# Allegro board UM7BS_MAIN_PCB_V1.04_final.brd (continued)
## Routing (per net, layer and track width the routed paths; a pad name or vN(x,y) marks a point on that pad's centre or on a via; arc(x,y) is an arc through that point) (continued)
MDI2-: length 17.8
  LAY3 w0.102: v1(116.23,38.89) 116.36,39.02 116.36,39.11 116.21,39.26 112.69,39.26 111.58,38.15 111.58,36.05 111.18,35.65 v1(110.17,35.65)
  BOTTOM w0.101: v1(116.23,38.89) 116.56,39.22 116.64,39.29 117.64,39.29 117.73,39.2 U22.8
  BOTTOM w0.102: U24.8 106.67,32.7 107.15,33.19 109.08,33.19 109.49,33.6 109.49,35.56 109.71,35.78 110.04,35.78 v1(110.17,35.65)
MDI3+: length 13.2
  LAY3 w0.102: v1(116.87,40.09) 116.76,40.2 116.76,40.64 116.34,41.06 109.91,41.06 109.82,41.14 108.66,41.14 v1(108.52,41.28)
  BOTTOM w0.101: U22.10 117.63,40 117.49,40.14 116.92,40.14 v1(116.87,40.09)
  BOTTOM w0.102: U24.1 106.71,41.59 107.3,41 108.24,41 v1(108.52,41.28)
MDI3-: length 13.1
  LAY3 w0.102: v1(108.52,40.64) 108.66,40.78 109.67,40.78 109.76,40.69 116.19,40.69 116.39,40.49 116.39,40.25 v1(116.23,40.09)
  BOTTOM w0.101: v1(116.23,40.09) 116.64,40.49 117.64,40.49 117.73,40.4 U22.11
  BOTTOM w0.102: U24.2 106.68,40.32 107.06,40.7 108.46,40.7 v1(108.52,40.64)
MIC1L-VREFO: length 10.9
  LAY4 w0.305: v1(24.28,27.44) 23.02,28.7 23.02,31.35 21.67,32.7 21.67,34.39 21.01,35.04 v1(20.79,35.04)
  BOTTOM w0.178: v1(20.79,35.04) U25.31
  BOTTOM w0.305: v1(24.28,27.44) 24.28,27.43 R337.2
MIC1R-VREFO: length 9
  LAY4 w0.305: v1(20.73,27.46) 21.11,27.85 21.11,34.13 v1(20.79,34.45)
  BOTTOM w0.178: v1(20.79,34.45) 20.92,34.45 21.12,34.64 U25.30
  BOTTOM w0.305: R335.2 v1(20.73,27.46)
MIC2-VREFO: length 13.9
  LAY4 w0.305: v1(24.31,26.71) 20.75,26.71 20.08,27.39 20.08,33.56 v1(20.48,33.97)
  BOTTOM w0.178: v1(20.48,33.97) 20.99,33.97 21.26,34.24 U25.29
  BOTTOM w0.305: v1(24.31,26.71) 24.93,27.33 R333.1
MIC_SEL_DET: length 99.7
  LAY3 w0.102: v1(42.25,74.8) 42.25,73.91 33.84,65.5 33.84,47.05 30.76,43.97 24.64,43.97 24.28,44.33 21.63,44.33 21.25,43.95 21.25,37.84 19.56,36.16 19.56,27.58 20.88,26.26 25.67,26.26 v1(26.75,25.17)
  BOTTOM w0.102: R404.2 44.51,75.08 44.23,74.8 v1(42.25,74.8)
  BOTTOM w0.254: R340.1 26.76,25.18 v1(26.75,25.17) 26.05,25.17 R349.1 25.79,25.32 Q36.1 26.73,23.09 28.47,23.09 30.05,21.51 37.15,21.51 38.29,20.37 38.29,15.85 36.4,13.96 J2.6
MIC_SEL_SPDIF: length 86
  LAY3 w0.102: v1(50.95,76.13) 51.66,75.42 51.66,61.33 51.13,60.81 51.13,59.97 51.39,59.71 51.39,55.83 50.72,55.16 50.72,46.45 v1(49.41,45.14)
  LAY4 w0.102: v1(27.32,22.03) 28.65,22.03 34.88,28.26 34.88,37.48 v1(31.71,40.64) ; v1(49.41,45.14) 48.58,44.31 31.65,44.31 v1(31.48,44.13)
  BOTTOM w0.102: v1(31.48,44.13) 31.19,43.85 31.19,42.86 30.68,42.35 30.68,41.1 R346.2 ; R346.2 31.14,40.38 28.36,37.61 27.79,37.61 27.66,37.74 U25.48 ; R346.2 v1(31.71,40.64) ; R450.2 50.94,76.12 v1(50.95,76.13) ; Q36.3 v1(27.32,22.03)
OVPA: length 36.6
  TOP w0.305: v1(121.9,84.01) 121.8,84.01 121.38,84.42 121.38,87.1 121,87.48 117.84,87.48 117.26,88.06 109.3,88.06 108.51,88.84 108.51,93.84 107.18,95.17 107.18,97.46 108.43,98.71 114.06,98.71
  BOTTOM w0.305: v1(121.9,84.01) 123.73,84.01 123.98,84.25 U41.7
PCIE_LAN_WAKE#: length 42.8
  LAY3 w0.102: v1(132.77,43.5) 143.7,43.5 146.63,46.43 154.99,46.43 157.31,48.75 v1(157.31,49.56)
  BOTTOM w0.102: R95.2 156.76,56.58 158.3,55.04 158.3,51.13 157.31,50.14 v1(157.31,49.56) ; v1(132.77,43.5) 129.73,40.47 R304.2
PCIE_RXN0_LAN: length 61.8
  TOP w0.089: v1(175.4,59.63) 175.63,59.41 U1.J20
  LAY3 w0.112: v1(175.4,59.63) 175.03,59.26 175.03,58.99 174.71,58.66 172.84,58.66 171.71,57.53 167.75,57.53 166.81,58.46 163.04,58.46 160.7,56.12 160.7,54.78 157.48,51.56 157.48,51.03 157.12,50.67 156.77,50.67 154.66,48.56 152.05,48.56 151.67,48.95 146.25,48.95 142.08,44.78 130.11,44.78 128.6,46.29 126.38,46.29 v1(126.12,46.03)
  BOTTOM w0.124: v1(126.12,46.03) 125.84,46.3 125.1,46.3 124.93,46.13 124.93,45.24 C346.1
PCIE_RXN1_WLAN: length 169.3
  TOP w0.089: v1(173.88,59.63) 174.2,59.3 U1.F20
  TOP w0.124: CN26.43 238.92,18.27 239.05,18.4 239.52,18.4 240.34,19.22 240.34,20.43 240.47,20.55 240.62,20.55 v1(240.89,20.28)
  LAY3 w0.089: v1(173.88,59.63) 173.67,59.84 173.67,59.9 173.79,60.02 177.75,60.02 178.08,60.35 178.08,60.76 178.76,61.44 178.76,62.57 179.1,62.91 179.11,62.91 179.12,62.92 179.14,62.92 179.14,62.91 179.21,62.98 179.21,63.05 179.21,63.05 179.21,63.07
  LAY3 w0.099: 179.21,63.07 179.21,67.71 179.44,67.94 179.44,74.54 179.45,74.54 179.45,74.57
  LAY3 w0.112: v1(240.89,20.28) 240.52,20.65 239.52,20.65 238.01,22.16 238.01,35.78 226.37,47.42 226.37,90.82 218.05,99.13 216.97,99.13 215.88,98.05 208.01,98.05 201.23,91.27 188.71,91.27 187.53,90.08 187.53,84.23 185.22,81.93 181.52,81.93 179.15,79.56 179.15,75.45 179.45,75.15 179.45,74.57
PCIE_RXP0_LAN: length 61.8
  TOP w0.089: v1(174.52,59.63) 174.92,59.23 U1.G20
  LAY3 w0.112: v1(126.12,46.8) 126.38,46.53 128.7,46.53 130.21,45.02 141.98,45.02 146.15,49.18 151.77,49.18 152.15,48.8 154.56,48.8 156.67,50.91 157.02,50.91 157.24,51.12 157.24,51.66 160.46,54.88 160.46,56.22 162.94,58.7 166.91,58.7 167.85,57.76 171.61,57.76 172.75,58.9 174.61,58.9 174.79,59.09 174.79,59.35 v1(174.52,59.63)
  BOTTOM w0.124: C347.1 124.68,45.24 124.68,46.24 124.99,46.55 125.87,46.55 v1(126.12,46.8)
PCIE_RXP1_WLAN: length 169.4
  TOP w0.089: U1.D20 173.53,59.34 v1(173.25,59.63)
  TOP w0.124: CN26.41 238.9,18.77 239.02,18.65 239.42,18.65 240.09,19.33 240.09,20.53 240.36,20.8 240.8,20.8 v1(240.89,20.89)
  LAY3 w0.089: v1(173.25,59.63) 173.45,59.84 173.45,59.99 173.7,60.24 177.66,60.24 177.86,60.44 177.86,60.81 178.57,61.51 178.57,62.65 178.97,63.05 178.97,63.05 178.99,63.07
  LAY3 w0.099: 179.21,74.57 179.21,74.54 179.21,74.54 179.21,68.03 178.99,67.81 178.99,63.07
  LAY3 w0.112: v1(240.89,20.89) 239.62,20.89 238.25,22.26 238.25,35.88 226.6,47.52 226.6,90.92 218.15,99.37 216.87,99.37 215.78,98.29 207.91,98.29 201.13,91.5 188.61,91.5 187.29,90.18 187.29,84.33 185.12,82.17 181.42,82.17 178.91,79.66 178.91,75.35 179.21,75.05 179.21,74.57
PCIE_TXN0_LAN: length 61.7
  TOP w0.124: C4.2 167.97,61.28 167.54,61.28 167.53,61.27 164.83,61.27 v1(164.48,60.92)
  LAY3 w0.112: v1(128.3,48.45) 128.44,48.59 128.44,48.71 128.55,48.82 131.88,48.82 133.76,50.71 152.88,50.71 156.05,53.87 157.19,53.87 158.66,55.34 158.66,56.95 163,61.29 163.92,61.29 164.29,60.92 v1(164.48,60.92)
  BOTTOM w0.124: v1(128.3,48.45) 128.3,48.35 128.18,48.22 127.95,48.22 127.82,48.35 127.82,48.59 127.69,48.71 121.38,48.71 120.52,47.86 120.52,43.28 120.66,43.13 120.66,42 120.73,41.94 U22.18
PCIE_TXN1_WLAN: length 186.4
  TOP w0.124: CN26.37 238.8,19.77 238.93,19.9 239.31,19.9 239.59,20.18 239.59,21.8 240.45,22.66 240.45,23.79 240.16,24.08 239.7,24.08 v1(239.53,24.25) ; v1(167.39,98.62) 167.16,98.39 167.16,97.27 166.72,96.83 166.72,92.06 164.37,89.7 162.85,89.7 160.52,87.37 160.52,70.48 162.03,68.97 163.61,68.97 163.85,69.21 C6.2
  LAY3 w0.112: v1(239.53,24.25) 239.66,24.12 240.8,24.12 241.99,25.32 241.99,34.67 228.39,48.27 228.39,92.06 218.74,101.71 218.03,101.71 217.68,101.35 214.48,101.35 214.05,101.78 211.17,101.78 209.13,99.74 190.97,99.74 190.04,100.67 168.76,100.67 167.15,99.06 167.15,98.87 v1(167.39,98.62)
PCIE_TXP0_LAN: length 61.3
  TOP w0.124: v1(164.48,61.53) 164.72,61.53 164.72,61.52 167.86,61.52 C3.2
  LAY3 w0.112: v1(164.48,61.53) 162.9,61.53 158.42,57.05 158.42,55.43 157.1,54.11 155.95,54.11 152.78,50.94 133.67,50.94 131.78,49.06 128.44,49.06 v1(128.3,49.2)
  BOTTOM w0.124: v1(128.3,49.2) 128.07,48.97 121.27,48.97 120.27,47.96 120.27,43.17 120.41,43.03 120.41,42.05 120.33,41.97 U22.17
PCIE_TXP1_WLAN: length 187.3
  TOP w0.124: CN26.35 238.84,20.27 238.96,20.15 239.2,20.15 239.34,20.28 239.34,21.9 240.2,22.76 240.2,23.69 240.05,23.83 239.72,23.83 v1(239.53,23.64) ; C5.2 163.85,68.44 163.57,68.71 161.92,68.71 160.27,70.37 160.27,87.47 162.75,89.96 164.26,89.96 166.47,92.16 166.47,96.93 166.91,97.38 166.91,98.37 v1(166.66,98.62)
  LAY3 w0.112: v1(239.53,23.64) 239.78,23.89 240.9,23.89 242.23,25.22 242.23,34.77 228.63,48.37 228.63,92.16 218.84,101.95 217.94,101.95 217.58,101.59 214.58,101.59 214.15,102.02 211.07,102.02 209.03,99.98 191.07,99.98 190.14,100.91 168.66,100.91 166.91,99.16 166.91,98.87 v1(166.66,98.62)
PCIE_WIFI_WAKE#: length 178.3
  LAY3 w0.102: v1(189.18,90.72) 201.79,90.72 208.62,97.55 217.02,97.55 218.21,96.37 219.46,96.37 225.42,90.41 225.42,46.31 235.12,36.61 v1(235.12,14.78)
  LAY4 w0.102: v1(159.74,60.19) 160.32,60.19 167.75,67.63 167.75,71.95 169.81,74.01 169.81,79.19 172.32,81.7 177.46,81.7 179.63,79.54 181.38,79.54 182.99,81.15 184.13,81.15 189.28,86.3 189.28,90.63 v1(189.18,90.72)
  BOTTOM w0.102: v1(159.74,60.19) 157.66,60.19 156.76,59.29 R97.2 ; R787.1 v1(235.12,14.78)
PD#: length 10.8
  LAY4 w0.102: v1(32.13,36.29) 30.37,38.04 v1(28.24,38.04)
  BOTTOM w0.102: U26.4 33.32,35.1 v1(32.13,36.29)
  BOTTOM w0.114: U25.47 26.63,37.96 26.97,38.31 27.98,38.31 v1(28.24,38.04)
PERSTB: length 3.1
  BOTTOM w0.114: R306.1 125.37,42.13 125.37,41.65 124.53,40.8 U22.25
PM_BATLOW#: length 112.9
  TOP w0.089: 168.41,57.59 168.46,57.59 168.89,57.15 R122.1
  TOP w0.102: R122.1 169.98,57.15 170.75,56.38 171.37,56.38 171.48,56.49 172.02,56.49 172.12,56.6 172.36,56.6 172.67,56.29 U1.C14 ; v1(149.65,58.88) 149.9,58.63 163.77,58.63 164.81,57.59 168.41,57.59
  LAY3 w0.102: v1(85.97,56.4) 85.99,56.38 95.61,56.38 97.43,58.19 103,58.19 105.23,60.42 110.48,60.42 113.66,57.24 115.63,57.24 116.61,58.22 122.12,58.22 123.02,57.32 125.08,57.32 125.33,57.07 146.28,57.07 148.19,58.98 149.55,58.98 v1(149.65,58.88)
  LAY4 w0.102: v1(85.97,56.4) 84.61,57.75 79.61,57.75 78.53,58.83 72.64,58.83 71.36,60.11 v1(69.03,60.11)
  BOTTOM w0.102: v1(69.03,60.11) R448.1 R447.1
PM_RSMRST#: length 133.3
  TOP w0.102: U1.F18 173.88,57.92 v1(173.88,57.72)
  LAY3 w0.102: v1(152.19,68.88) 142.63,68.88 137.4,74.12 124.88,74.12 124.08,74.91 121.05,74.91 120.74,74.6 118.56,74.6 118.25,74.91 103.43,74.91 100.88,72.36 84.44,72.36 84.11,72.03 77.57,72.03 77.23,72.36 74.34,72.36 71.77,69.8 71.77,64.08 v1(71.87,63.98)
  LAY4 w0.127: v1(152.19,68.88) 152.19,68.19 158.49,61.88 158.49,60.13 159.55,59.07 167.03,59.07 167.46,59.5 v1(167.46,60.59)
  BOTTOM w0.102: v1(71.87,63.98) 71.87,63.49 70.85,62.47 68.08,62.47 67.39,61.78 R591.2 ; v1(173.88,57.72) 173.44,58.17 172.55,58.17 172.38,58 172.14,58
  BOTTOM w0.114: R393.1 65.14,63.93 65.72,63.93 66,64.21 66.49,64.21 66.83,63.87 66.83,62.34 R591.2 ; R82.1 170.22,60.46 170.86,59.81 170.86,58.56 171.42,58 172.14,58
  BOTTOM w0.127: v1(167.46,60.59) 167.46,60.75 167.69,60.98 169.5,60.98 R82.1
PM_SLP_S0IX#: length 105.3
  LAY3 w0.102: v1(58.95,75.74) 58.95,75.69 58.27,75.01 58.27,69.47 56.69,67.88 56.69,62 57.74,60.95 57.74,59.36 56.69,58.31 56.69,54.84 v1(56.96,54.57) ; v1(106.76,80.87) 104.73,80.87 103.72,79.85 102.2,79.85 99.86,77.51 88.82,77.51 86.94,79.39 77.51,79.39 71.05,72.94 71.05,58.16 71.86,57.35 v1(71.86,56.39)
  LAY4 w0.102: v1(56.96,54.57) 57.21,54.81 60.95,54.81 61.62,55.49 69.76,55.49 70.66,56.39 v1(71.86,56.39)
  BOTTOM w0.102: C566.2 75.27,55.78 72.46,55.78 v1(71.86,56.39) ; R225.2 108.65,80.87 v1(106.76,80.87)
  BOTTOM w0.114: R442.1 v1(58.95,75.74) ; C566.2 75.91,57.17 76.17,57.43 U6.7
PM_SLP_S3#: length 157.2
  LAY3 w0.203: v1(72.89,58.12) 73.33,57.68 77.3,57.68 79.14,55.84 80.15,55.84 81.22,56.9 81.22,59.04 81.76,59.58 83.28,59.58 83.49,59.37 91.2,59.37 94.08,62.26 115.17,62.26 117.14,60.28 120.18,60.28 120.83,59.64 129.93,59.64 130.89,60.6 138.25,60.6 v1(138.57,60.28)
  LAY4 w0.203: v1(160.09,67.44) 164.81,67.44 165.68,68.31 v1(167.07,68.31) ; v1(142.98,45.04) 143.56,45.62 143.56,50.42 138.89,55.09 138.89,59.96 v1(138.57,60.28) ; v1(72.89,58.12) 72.31,58.7 68.05,58.7 67.76,58.41 52.96,58.41 52.36,59.02 v1(50.46,59.02)
  BOTTOM w0.114: C23.2 75.93,58.23 75.94,58.23 U6.9
  BOTTOM w0.152: v1(72.89,58.12) 73.23,57.78 75.04,57.78 75.27,58.01 C23.2
  BOTTOM w0.203: v1(138.57,60.28) 143.15,60.28 144.25,61.38 148.55,61.38 149.04,60.9 154.69,60.9 159.09,65.3 R219.1 159.22,66.51 160.09,67.38 v1(160.09,67.44) ; U31.70 49.61,59.86 v1(50.46,59.02) ; R557.1 142.97,45.04 v1(142.98,45.04) ; R3112.2 168.11,68.68 167.75,68.31 v1(167.07,68.31)
PM_SLP_S4#: length 32.8
  LAY4 w0.152: v1(72.55,56.38) 72.04,56.89 52.78,56.89 51.55,58.12 49.93,58.12 v1(48.7,59.34)
  BOTTOM w0.152: v1(72.55,56.38) 72.8,56.13 74.92,56.13 75.27,56.47 C24.2 75.55,57.21 76.17,57.83 U6.8 ; v1(48.7,59.34) 48.59,59.46 U31.69
PMC_ACPRESENT: length 9.5
  TOP w0.102: U1.C13 172.46,55.95 172.15,55.95 172.01,56.08 171.68,56.08
  TOP w0.114: v1(166.41,56.87) 166.88,56.4 170.02,56.4 170.47,55.95 171.55,55.95 171.68,56.08
  BOTTOM w0.102: v1(166.41,56.87) 166.35,56.8 R127.2 165.77,56.26 165.27,56.77 Q8.3
PMC_PLTRST: length 133.4
  LAY3 w0.102: v1(183.32,37.76) 180.55,37.76 180.36,37.56 176.96,37.56 175.17,39.35 175.17,41.18 173.79,42.56 173.79,45.89 ; v1(142.8,63.93) 134.46,72.27 128.56,72.27 128.36,72.07 119.36,72.07 118.64,71.35 118.64,67.43 114.49,63.29 93.11,63.29 91.3,61.49 83.38,61.49 v1(82.94,61.04)
  LAY3 w0.127: v1(166.96,52.03) 166.96,51.65 167.81,50.8 168.36,50.8 168.93,50.24 170.74,50.24 171.57,49.41 171.99,49.41 173.79,47.61 173.79,45.89
  LAY4 w0.127: v1(166.96,52.03) 165.91,52.03 162.52,55.41 159.86,55.41 153.33,61.94 149.19,61.94 148.77,62.37 144.36,62.37 v1(142.8,63.93)
  BOTTOM w0.102: v1(82.94,61.04) 82.47,61.04 TP15.1 80.72,59.3 79.29,59.3 78.63,58.63 U6.2
  BOTTOM w0.114: R166.1 183.34,37.74 v1(183.32,37.76) ; v1(166.96,52.03) 166.55,51.62 R602.2
PMC_PWRBTN#: length 118.7
  TOP w0.102: U1.M16 176.67,56.9 v1(176.67,56.83)
  TOP w0.114: R415.1 78.55,67.88 79.67,66.76 v1(79.67,66.74)
  LAY3 w0.102: v1(79.67,66.74) 84.85,66.74 86.84,64.75 114.88,64.75 117.88,67.75 117.88,71.67 119.1,72.89 127.66,72.89 127.86,73.09 136.86,73.09 147,62.95 v1(147,62.79)
  LAY4 w0.102: v1(166.86,55.52) 166.09,55.52 164.7,56.9 158.89,56.9 153.42,62.37 149.34,62.37 148.93,62.79 v1(147,62.79)
  BOTTOM w0.102: v1(166.86,55.52) 166.86,54.68 167.93,53.61 169.86,53.61 170.26,54.02 R121.2 171.4,54.32 171.72,54.64 171.72,55.33 172.59,56.2 176.04,56.2 v1(176.67,56.83)
  BOTTOM w0.114: v1(79.67,66.74) 79.18,67.23 U30.4
PMC_PWRBTN#_EC: length 33.9
  TOP w0.114: v1(75.05,67.5) 75.43,67.88 R415.2
  LAY4 w0.102: v1(55.6,67.9) 55.75,67.76 74.79,67.76 v1(75.05,67.5)
  BOTTOM w0.114: U30.8 75.95,67.23 75.68,67.5 v1(75.05,67.5) 75.27,67.28 R416.1 ; v1(55.6,67.9) 55.6,65.59 58.04,63.15 60.5,63.15 60.81,63.46 U31.18
PMC_RSTBTN: length 153.6
  TOP w0.102: 184.55,48.85 184.55,49.34 184.29,49.6 184.29,50.04 U1.AF2
  TOP w0.114: v1(185.69,44.08) 185.27,44.51 185.27,46.28 R119.1 185.87,47.52 184.55,48.85 ; v1(79.08,67.96) 78.26,68.77 R412.1 R118.1 R124.2
  LAY3 w0.102: v1(185.69,44.08) 185.54,43.93 185.54,38.28 184.59,37.34 184.59,36.19 183.77,35.37 175.9,35.37 171.92,39.34 171.92,40.86 165.19,47.6 v1(164.72,47.6) ; v1(147.5,60.49) 147.48,60.5 147.48,62.92 136.96,73.45 127.87,73.45 127.67,73.25 119.09,73.25 117.67,71.83 117.67,67.83 114.79,64.95 87.99,64.95 84.99,67.96 v1(79.08,67.96)
  LAY4 w0.102: v1(164.72,47.6) 163.45,48.86 159.05,48.86 157.45,50.46 156.75,50.46 152.96,54.25 152.96,59.22 151.7,60.49 v1(147.5,60.49)
  BOTTOM w0.114: U30.3 78.75,67.63 v1(79.08,67.96)
PMC_SLP_S0IX: length 150
  TOP w0.102: v1(85.62,60.93) 85.62,61.09 94.42,69.89 103.23,69.89 106.2,66.92 106.2,52.76 106.78,52.18 109.31,52.18 111.02,53.89 120.21,53.89 122.67,56.35 137.04,56.35 137.98,57.28 148.19,57.28 v1(148.6,57.68)
  TOP w0.114: v1(157.26,27.91) 157.75,27.91 159.24,26.43 U11.61 ; R206.1 153.67,17.51 v1(153.23,17.51)
  LAY3 w0.102: v1(157.26,27.91) 157.91,27.26 157.91,19.13 157.01,18.23 153.95,18.23 v1(153.23,17.51)
  LAY4 w0.102: v1(157.26,27.91) 157.38,28.02 157.38,33.85 153.78,37.44 153.78,46.03 148.6,51.21 v1(148.6,57.68)
  BOTTOM w0.102: v1(85.62,60.93) 85.62,57.55 83.1,55.03 79.11,55.03 78.16,55.97 R605.2 78.16,56.7 U6.5
PMC_SLP_S3: length 126.3
  TOP w0.114: v1(157.27,27.36) 157.92,27.36 158.84,26.44 U11.62 ; v1(153.29,18.12) 153.46,18.12 R203.1
  LAY3 w0.102: v1(82.21,58.78) 91.77,58.78 93.59,60.61 102.9,60.61 103.58,61.3 115.15,61.3 116.86,59.58 117.92,59.58 118.56,58.94 125.71,58.94 126.93,57.72 137.37,57.72 140.2,60.54 145.76,60.54 146.63,59.67 v1(147.95,59.67) ; v1(153.29,18.12) 153.64,18.47 156.68,18.47 157.66,19.45 157.66,26.96 v1(157.27,27.36)
  LAY4 w0.102: v1(147.95,59.67) 147.95,59.19 148.99,58.15 148.99,51.25 154.26,45.97 154.26,37.29 157.67,33.88 157.67,27.76 v1(157.27,27.36)
  BOTTOM w0.102: U6.3 79.08,58.23 R604.2 79.64,58.79 TP12.1
PMC_SLP_S4: length 112.4
  TOP w0.114: U11.63 158.44,26.44 158.08,26.8 v1(157.25,26.8)
  LAY3 w0.102: v1(83.56,57.18) 83.65,57.28 95.27,57.28 96.6,58.62 102.97,58.62 105.03,60.68 110.56,60.68 113.71,57.52 115.41,57.52 116.34,58.46 122.28,58.46 123.15,57.59 126.14,57.59 126.44,57.3 145.85,57.3 v1(147.39,58.84)
  LAY4 w0.102: v1(147.39,58.84) 148.2,58.04 148.2,51.18 152.45,46.93 152.45,38.49 156.56,34.37 156.56,27.49 v1(157.25,26.8)
  BOTTOM w0.102: U6.4 78.83,57.83 R603.2 80.48,56.19 TP13.1 81.45,56.19 81.69,56.43 82.81,56.43 v1(83.56,57.18)
PMC_SUS_STAT#: length 116.9
  TOP w0.102: U1.D14 173.53,56.1 v1(173.25,55.82) ; R440.1 78.01,61.42 78.65,62.06 v1(78.65,62.25)
  LAY3 w0.102: v1(78.65,62.25) 90.86,62.25 92.25,63.64 114.34,63.64 118.28,67.58 118.28,71.5 119.26,72.47 128.03,72.47 128.23,72.67 135.18,72.67 142.8,65.05 v1(142.8,64.53)
  LAY4 w0.102: v1(166.95,53.56) 166.95,54.41 167.92,55.38 167.92,57.25 167.61,57.56 158.77,57.56 153.58,62.75 149.28,62.75 147.98,64.05 143.28,64.05 v1(142.8,64.53)
  BOTTOM w0.102: v1(166.95,53.56) 167.2,53.31 170.15,53.31 170.84,54 171.45,54 172.03,54.58 172.03,54.95 172.9,55.82 v1(173.25,55.82)
  BOTTOM w0.114: U32.5 78.41,62.76 78.65,62.52 v1(78.65,62.25)
PMC_SUSPWRDNACK: length 159.2
  TOP w0.102: 183.12,49.57 183.39,49.83 183.39,49.95 183.54,50.1 183.54,50.4 U1.AE3 ; v1(184.44,44.38) 184.01,44.81 184.01,46.46 R86.1
  TOP w0.114: 183.12,49.57 183.12,48.43 184.44,47.11 R86.1
  LAY3 w0.102: v1(184.44,44.38) 184.82,44.01 184.82,38.51 183.92,37.61 183.92,36.64 183.39,36.12 176.28,36.12 173.9,38.5 173.9,39.94 171.24,42.59 171.24,44.97 166.49,49.71 v1(164.45,49.71) ; v1(72.56,64.37) 73.68,65.48 73.68,70.58 75.01,71.92 76.18,71.92 76.57,71.53 84.34,71.53 84.73,71.92 101,71.92 103.48,74.4 107.65,74.4 108.54,73.51 127.27,73.51 127.52,73.75 137.18,73.75 148.14,62.79 v1(148.14,60.91)
  LAY4 w0.102: v1(164.45,49.71) 158.49,49.71 157.54,50.66 156.84,50.66 153.27,54.23 153.27,59.64 152.13,60.78 148.27,60.78 v1(148.14,60.91)
  BOTTOM w0.114: v1(72.56,64.37) 72.29,64.64 R429.1 71.1,65.11 Q43.1
PMIC_EN: length 156.2
  TOP w0.102: v1(148.63,19.44) 148.99,19.08 151.15,19.08 151.92,18.31 R553.2
  TOP w0.114: R553.2 153.38,19.06 155.5,19.06 156.82,20.39 U11.13
  LAY3 w0.102: v1(88.97,60.28) 91.45,60.28 93.9,62.73 115.39,62.73 v1(116.57,61.55) 117.54,60.58 120.52,60.58 121.1,60 129.42,60 130.57,61.15 137.35,61.15 v1(138.58,62.38)
  LAY4 w0.102: v1(148.63,19.44) 148.63,27.2 146.77,29.05 146.77,37.97 148.94,40.13 148.94,44.91 148.5,45.35 148.5,47.92 139.96,56.46 139.96,61.01 v1(138.58,62.38) ; v1(50.01,52.97) 50.5,53.46 61.38,53.46 62.42,54.51 80.22,54.51 80.85,55.13 86.13,55.13 88.97,57.98 v1(88.97,60.28)
  BOTTOM w0.102: R552.2 v1(50.01,52.97)
  BOTTOM w0.203: v1(116.57,61.55) 116.73,61.38 R187.2
PMU_SUSCLK: length 245.6
  TOP w0.089: U1.C15 172.51,56.87 172.23,56.87 171.88,57.22 170.59,57.22 170.01,57.8 168.41,57.8
  TOP w0.102: v1(166.05,58.01) 166.26,57.8 168.41,57.8
  LAY3 w0.102: v1(166.05,58.01) 165.92,57.88 165.07,57.88 157.25,50.06 156.86,50.06 154.81,48 150.4,48 149.17,46.77 147.34,46.77 v1(147.28,46.83) 146.4,46.83 145.19,45.61 144.68,45.61 143.04,43.97 122.92,43.97 118.47,48.42 98.06,48.42 94.52,44.89 v1(94.32,44.89) ; v1(234.05,16.47) 227.65,10.07 196.53,10.07 v1(195.68,10.92)
  LAY4 w0.102: v1(142.82,12.1) 142.82,17.7 145.45,20.32 145.45,24.02 144.48,24.98 140.28,24.98 139.47,25.79 139.47,27.08 144.44,32.05 144.44,43.98 v1(147.28,46.83)
  BOTTOM w0.102: v1(94.32,44.89) 90.19,40.76 88.98,40.76 84.64,36.42 R561.1 ; v1(195.68,10.92) 195.48,10.92 192.61,8.06 152.13,8.06 149.8,10.39 145.91,10.39 144.2,12.1 v1(142.82,12.1) ; v1(234.05,16.47) 234.01,16.51 R788.2
POWSW#: length 25.8
  TOP w0.305: SW1.1 121.46,10.63 v1(123.74,10.63)
  BOTTOM w0.305: R499.1 139.03,20.98 137.72,20.98 D22.N D23.N 136.93,18.96 136.07,18.09 129.48,18.09 123.74,12.36 v1(123.74,10.63)
PROCHOT#_EC: length 6.6
  TOP w0.102: U33.2 50.39,62.05 51.02,61.42 R464.2 R456.2 49.58,61.33 v1(49.46,61.45)
  BOTTOM w0.102: U31.76 48.64,62.26 v1(49.46,61.45)
PS_LATCH#: length 8.3
  BOTTOM w0.305: R500.1 133.64,21.43 134.1,20.98 D22.P 135.97,20.98 136.42,21.42 Q45.1 136.42,23.84 137.57,24.99 R498.1
PSELF: length 3.1
  TOP w0.102: U9.17 169.8,93.33 R178.1 R177.2
PSMS: length 2
  BOTTOM w0.102: U95.20 73.27,96.98 72.32,97.93 R800.1
PWM: length 3.7
  BOTTOM w0.305: U41.16 118.89,89.42 R531.1 R530.2 R534.1 R528.1
PWR_LED_WHITE: length 98.3
  TOP w0.102: v1(101.93,10.33) 101.93,14.42 Q16.1
  LAY3 w0.102: v1(51.13,54.18) 51.13,50.78 53.15,48.76 53.15,44.57 51.89,43.3 v1(51.89,36.99)
  LAY4 w0.102: v1(51.89,36.99) 54.78,34.1 54.78,16.95 57.86,13.86 67.14,13.86 70.8,10.2 89.3,10.2 91.87,12.77 96.36,12.77 98.93,10.2 101.8,10.2 v1(101.93,10.33)
  BOTTOM w0.102: v1(51.13,54.18) 51.13,54.19 U31.56
PWR_SW: length 17.6
  TOP w0.305: v1(76.26,99.19) 73.85,99.19 71.3,96.65 CN23.4
  BOTTOM w0.305: U95.24 75.27,97.33 76.26,98.31 C704.1 v1(76.26,99.19)
PWRONLATCHG: length 15.5
  TOP w0.305: Q44.4 138.26,19.22 v1(139.38,18.1)
  BOTTOM w0.305: R498.2 138.53,25.52 C465.1 R496.1 141.57,25.52 141.97,25.12 141.97,18.83 141.24,18.1 v1(139.38,18.1)
R_OUT+: length 1.6
  TOP w0.508: CN12.1 R361.1
R_OUT-: length 1.6
  TOP w0.508: CN12.2 R360.1
REXT: length 2
  BOTTOM w0.102: U16.26 150.71,92.27 149.81,91.37 R267.2
RLV_AMP: length 2.5
  BOTTOM w0.102: U16.27 150.31,92.18 149.91,91.77 149.23,91.77 149.04,91.59 R266.2
RLV_CFG: length 2.4
  BOTTOM w0.102: U16.22 152.31,91.35 R275.2 R274.1
RLV_LNK: length 10.4
  TOP w0.203: v1(152.6,88.3) 152.48,88.18 v1(152.48,84.19)
  BOTTOM w0.152: v1(152.6,88.3) R273.1 152.6,91.83 152.71,91.95 U16.21
  BOTTOM w0.203: U18.7 152.16,83.67 152.48,83.99 v1(152.48,84.19)
RSET: length 5.7
  BOTTOM w0.114: U22.46 119.53,35.29 119.24,35 118.83,35 118.1,34.26 118.1,31.92 118.21,31.82 R297.1
RSMRST#_EC: length 2.6
  BOTTOM w0.114: R393.2 63.65,64.19 62.52,63.06 U31.19
RSMRST_PWRGD: length 179.2
  TOP w0.102: v1(153.8,14.65) 154.06,14.91 R208.1
  LAY3 w0.102: v1(47.78,70.03) 48.07,69.74 48.07,64.71 47.38,64.02 47.38,52.98 47.95,52.42 47.95,39.92 48.48,39.38 v1(48.48,37.27)
  LAY4 w0.102: v1(48.48,37.27) 48.84,37.62 57.9,37.62 58.63,36.9 67.91,36.9 69.21,38.2 87.08,38.2 97.11,48.23 105,48.23 106.88,46.35 106.88,19.29 110.85,15.32 127.55,15.32 130.51,12.35 141.05,12.35 141.72,11.67 143.13,11.67 145.63,14.17 152.23,14.17 152.71,14.65 v1(153.8,14.65)
  BOTTOM w0.114: v1(47.78,70.03) 47.55,70.26 U31.96
RSTZ: length 3.3
  BOTTOM w0.254: U95.22 74.27,98.09 C707.1 R802.2 R801.2
RTA: length 1
  BOTTOM w0.203: R958.2 U41.8
RUNTIME_SCI#_EC: length 21.3
  TOP w0.102: v1(76.75,66.18) 76.64,66.07 v1(69.7,66.07)
  TOP w0.114: R417.2 76.75,66.5 v1(76.75,66.18)
  LAY3 w0.102: v1(69.7,66.07) 69.7,59.15 v1(68.42,57.87)
  BOTTOM w0.102: v1(68.42,57.87) 67.91,58.38 R430.1 64.49,58.38 D10.P
  BOTTOM w0.114: v1(76.75,66.18) 76.76,66.19 U30.7
SA0_DIM0: length 4.8
  TOP w0.102: R147.1 210.15,42.62 R150.1 210.6,41.99 210.6,40.44 210.89,40.15 CN1.197
SA1_DIM0: length 3.6
  TOP w0.102: R590.1 209.37,39.29 R151.1
  TOP w0.114: R151.1 209.95,39.29 210.29,38.95 CN1.201
SATA_DEVSLP0: length 150.3
  TOP w0.102: R24.2 187.13,44.6 186.99,44.46 v1(186.99,43.44)
  LAY3 w0.102: v1(148.75,59.66) 148.34,59.24 146.26,59.24 145.26,60.24 140.23,60.24 137.49,57.5 126.6,57.5 126.24,57.87 123.48,57.87 122.62,58.72 118.17,58.72 117.65,59.25 115.78,59.25 114.06,60.97 104.37,60.97 102.82,59.42 92.82,59.42 91.2,57.8 83.41,57.8 82.93,57.33 82.93,53.47 76.6,47.14 v1(76.6,44.42) ; v1(186.99,43.44) 188.41,42.02 188.41,37.95 185.34,34.88 175.97,34.88 171.7,39.15 171.7,40.57 165.33,46.94 v1(164.74,46.94)
  LAY4 w0.102: v1(164.74,46.94) 164.15,47.53 160.1,47.53 157.41,50.21 156.71,50.21 152.72,54.21 152.72,58.77 151.32,60.16 149.25,60.16 v1(148.75,59.66)
  BOTTOM w0.102: R560.1 v1(76.6,44.42)
SATA_LED#: length 6.1
  TOP w0.102: U1.AH3 184.93,50.68 184.93,50.42 184.8,50.28 184.8,50.09 185.18,49.71 185.18,49.14 186.46,47.86 187.58,47.86 187.99,47.46 R22.1
SATA_RXN0: length 102.7
  TOP w0.101: v1(177.44,63.57) 177.44,63.47 U1.M28
  TOP w0.124: C263.2 91.41,46.97 93.04,46.97 v1(93.16,46.85)
  LAY3 w0.112: v1(93.16,46.85) 94.24,46.85 99.01,51.61 114.15,51.61 114.96,52.42 151.38,52.42 153.41,54.45 153.98,54.45 154.67,55.15 154.67,55.71 163,64.04 163,65.19 162.68,65.51 162.14,65.51 162.08,65.58 162.08,65.87 161.94,66.01 v1(161.72,66.01)
  BOTTOM w0.124: v1(161.72,66.01) 161.94,65.78 165.33,65.78 166.82,67.27 170.09,67.27 172.19,65.17 172.19,63.83 173,63.03 177.47,63.03 177.7,63.26 177.7,63.42 177.56,63.57 v1(177.44,63.57)
SATA_RXN1: length 106.7
  TOP w0.101: v1(176.67,63.57) 176.67,63.42 U1.K28
  TOP w0.124: C433.1 106.16,69.62 106.16,68.69 107.11,67.74 107.11,56.05 107.83,55.33 107.83,54.91 107.52,54.6 107.14,54.6 v1(107,54.47)
  LAY3 w0.089: 169.11,64.54 169.11,63.21 169.85,62.47 176.22,62.47 176.67,62.92 v1(176.67,63.57)
  LAY3 w0.112: v1(107,54.47) 108.76,54.47 109.94,53.28 150.94,53.28 156.36,58.71 156.36,59.45 159.13,62.21 159.13,69.53 160.78,71.19 165.42,71.19 169.11,67.5 169.11,64.54
SATA_RXP0: length 102.5
  TOP w0.101: v1(178.2,63.57) 177.76,63.13 U1.N28
  TOP w0.124: C171.2 91.28,47.65 91.71,47.22 92.91,47.22 93.08,47.39 93.08,47.54 v1(93.16,47.62)
  LAY3 w0.112: v1(93.16,47.62) 93.69,47.09 94.14,47.09 98.91,51.85 114.05,51.85 114.86,52.66 151.28,52.66 153.31,54.69 153.88,54.69 154.43,55.24 154.43,55.81 162.76,64.14 162.76,65.09 162.58,65.27 v1(161.72,65.27)
  BOTTOM w0.124: v1(161.72,65.27) 161.97,65.53 165.44,65.53 166.93,67.02 169.99,67.02 171.94,65.07 171.94,63.73 172.9,62.77 177.57,62.77 177.95,63.16 177.95,63.32 v1(178.2,63.57)
SATA_RXP1: length 106.6
  TOP w0.101: v1(175.91,63.57) 175.91,63.16 175.84,63.08 U1.J28
  TOP w0.124: v1(106.98,55.07) 107.19,54.85 107.42,54.85 107.58,55.02 107.58,55.22 106.85,55.94 106.85,67.64 105.91,68.59 105.91,69.62 C434.1
  LAY3 w0.089: v1(175.91,63.57) 176.15,63.57 176.46,63.26 176.46,63.01 176.13,62.68 169.94,62.68 169.32,63.3 169.32,64.44 169.33,64.45 169.33,64.52 169.34,64.53 169.34,64.54
  LAY3 w0.112: v1(106.98,55.07) 107.34,54.71 108.86,54.71 110.04,53.52 150.84,53.52 156.12,58.81 156.12,59.55 158.89,62.31 158.89,69.63 160.68,71.43 165.52,71.43 169.34,67.6 169.34,64.54
SATA_TXN0: length 104
  TOP w0.101: U1.B30 172.29,64.11 172.43,64.11 172.5,64.04 172.5,63.9 172.37,63.77 172.11,63.77 171.89,63.99 170.87,63.99 169.54,65.32 169.54,67.24 166.94,69.84
  TOP w0.124: v1(161.96,70.64) 162.26,70.34 162.26,70.17 162.59,69.84 166.94,69.84 ; C296.2 91.26,46.04 91.38,45.92 92.14,45.92 v1(92.3,46.08)
  LAY3 w0.112: v1(161.96,70.64) 162.04,70.56 162.04,69.18 164.62,66.59 164.62,64.49 157.45,57.32 157.45,56.66 155.91,55.11 155.6,55.11 152.3,51.8 132.74,51.8 131.76,50.83 114.49,50.83 113.98,50.32 98.59,50.32 94.16,45.89 92.49,45.89 v1(92.3,46.08)
SATA_TXN1: length 102.8
  TOP w0.101: U1.A29 171.14,63.58 v1(170.75,63.19)
  TOP w0.124: v1(108.5,56.25) 108.33,56.42 108.01,56.42 107.76,56.68 107.76,68.05 106.96,68.85 106.96,72.59 105.96,73.59 105.96,74.86 C432.1
  LAY3 w0.089: v1(170.75,63.19) 170.95,63.39 170.95,63.76 169.71,64.99 169.71,68.2 168.44,69.47 168.43,69.47 168.41,69.49
  LAY3 w0.112: 168.41,69.49 165.85,72.05 160.41,72.05 158.27,69.91 158.27,62.73 155.49,59.96 155.49,59.1 150.93,54.54 111.4,54.54 109.36,56.59 108.84,56.59 v1(108.5,56.25)
SATA_TXP0: length 104.1
  TOP w0.101: U1.C31 172.47,64.42 172.17,64.42 171.95,64.2 171.9,64.2 171.89,64.21 170.96,64.21 169.76,65.41 169.76,67.34 167.18,69.92 167.18,69.94 167.04,70.08 166.96,70.08 166.95,70.09 166.94,70.09
  TOP w0.124: 166.94,70.09 162.7,70.09 162.51,70.28 162.51,70.44 162.51,70.45 v1(162.7,70.64) ; C312.2 91.7,45.67 91.94,45.67 v1(92.3,45.31)
  LAY3 w0.112: v1(92.3,45.31) 92.64,45.65 94.26,45.65 98.69,50.08 114.08,50.08 114.59,50.59 131.86,50.59 132.84,51.56 152.4,51.56 155.7,54.87 156.01,54.87 157.69,56.56 157.69,57.22 164.86,64.39 164.86,66.69 162.28,69.27 162.28,70.36 162.48,70.56 162.62,70.56 v1(162.7,70.64)
SATA_TXP1: length 102.8
  TOP w0.101: v1(171.36,63.19) 171.47,63.3 172.01,63.3 172.25,63.53 172.55,63.53 U1.C29
  TOP w0.124: C429.1 106.22,74.87 106.22,73.7 107.21,72.7 107.21,68.95 108.01,68.16 108.01,56.78 108.12,56.68 108.29,56.68 v1(108.5,56.89)
  LAY3 w0.089: 168.58,69.66 168.6,69.64 168.6,69.62 169.93,68.29 169.93,65.08 171.16,63.85 171.16,63.39 v1(171.36,63.19)
  LAY3 w0.112: v1(108.5,56.89) 108.56,56.83 109.46,56.83 111.5,54.78 150.83,54.78 155.25,59.2 155.25,60.06 158.03,62.83 158.03,70.01 160.31,72.29 165.95,72.29 168.58,69.66
SD_CDZ: length 17.6
  TOP w0.102: v1(73.77,97.41) 72.61,96.25 72.61,92.86 74.96,90.51 80.37,90.51 81.68,89.2 CN23.11
  BOTTOM w0.102: U95.21 73.77,97.41 v1(73.77,97.41)
SD_CLK: length 7.6
  TOP w0.102: v1(72.21,90.75) 73.8,89.15 CN23.5
  BOTTOM w0.102: v1(72.21,90.75) 71.15,91.81 71.15,93.51 71.51,93.87 U95.14
SD_CMD: length 9.9
  TOP w0.102: v1(67.47,91.79) 66.3,90.62 CN23.2
  BOTTOM w0.102: v1(67.47,91.79) 70.06,94.37 U95.15
SD_D0: length 10.7
  TOP w0.102: v1(73.83,89.98) 74.15,89.66 78.45,89.66 78.8,89.31 CN23.7
  BOTTOM w0.102: v1(73.83,89.98) 72.02,91.79 U95.13
SD_D1: length 10.6
  TOP w0.102: v1(74.02,90.77) 74.82,89.97 79.65,89.97 80.43,89.19 CN23.8
  BOTTOM w0.102: v1(74.02,90.77) 72.77,92.02 U95.12
SD_D2: length 14.4
  TOP w0.102: CN23.9 61.3,89.06 65.06,92.81 v1(65.06,92.82)
  BOTTOM w0.102: U95.17 67.61,95.37 v1(65.06,92.82)
SD_D3: length 12
  TOP w0.102: CN23.1 63.8,89.67 v1(66.67,92.53)
  BOTTOM w0.102: U95.16 69.01,94.87 v1(66.67,92.53)
SD_WP: length 12.1
  TOP w0.102: CN23.10 82.97,89.18 82.72,89.43 82.03,89.43 80.61,90.84 75.4,90.84 v1(74.59,91.66)
  BOTTOM w0.102: v1(74.59,91.66) 74.2,91.66 73.77,92.08 U95.10
SDMMC1_RCLK: length 20.9
  TOP w0.089: v1(178.83,55.31) 179.22,55.7 U1.T13
  LAY3 w0.127: v1(178.83,55.31) 178.96,55.31 180.44,53.83 180.81,53.83 181.12,53.52 181.12,51.11 183.83,48.4 183.83,43.5 184,43.32 184,40.53 v1(182.57,39.09)
  BOTTOM w0.114: R598.1 182.6,39.06 v1(182.57,39.09)
SECURITY_FLASH: length 10.4
  TOP w0.102: 184.48,83.88 185.13,84.54 R61.2 ; 184.93,77.38 185.13,77.18 185.13,75.04 U1.AH52
  TOP w0.114: 184.93,77.38 184.93,82.01 R63.2 184.48,82.46 184.48,83.88
SENSOR: length 184.1
  TOP w0.102: R586.2 R585.2 197.21,98.1 v1(197.19,98.12)
  LAY3 w0.102: v1(56.02,84.32) 56.02,83.37 50.37,77.72 50.37,67.52 50.85,67.04 50.85,64.47 50.29,63.91 50.29,59.54 v1(48.66,57.91)
  LAY4 w0.102: v1(197.19,98.12) 160.08,98.12 157.77,95.81 145.76,95.81 145.49,96.07 114.47,96.07 112.98,94.58 94.5,94.58 90.97,98.12 82.54,98.12 73.29,88.86 61.36,88.86 56.83,84.32 v1(56.02,84.32)
  BOTTOM w0.102: v1(48.66,57.91) 47.94,57.91 47.59,58.26 U31.66
SLPS3#_CONTROL: length 3.6
  BOTTOM w0.305: Q19.3 155.55,69.96 155.55,71.77 R215.2 R217.2
SMB_CLK_S2: length 197.6
  TOP w0.114: CN1.202 222.12,38.65 223.9,36.87 223.9,19.01 v1(223.88,19) 223.9,18.98 223.9,16.37 v1(226.68,13.59)
  LAY3 w0.127: v1(114.49,44.3) 114.99,44.8 v1(117.69,44.8)
  LAY4 w0.127: v1(117.69,44.8) 118.94,43.55 126.27,43.55 126.87,44.15 130.57,44.15 134.51,40.21 134.51,34.41 127.86,27.76 127.86,16.27 128.94,15.2 129.28,15.2 v1(129.73,15.65)
  BOTTOM w0.102: R785.2 v1(226.68,13.59)
  BOTTOM w0.114: R70.2 114.49,43.74 v1(114.49,44.3) 114.25,44.55 U5.6 ; R310.2 v1(117.69,44.8)
  BOTTOM w0.127: v1(223.88,19) 208.38,19 206.19,16.8 203.09,16.8 201.55,18.34 201.55,19.17 195.97,24.75 191.56,24.75 189.23,22.42 189.23,13.66 184.44,8.88 152.4,8.88 150.12,11.16 147.37,11.16 145.44,13.09 131.77,13.09 129.73,15.13 v1(129.73,15.65)
SMB_DATA_S2: length 200.7
  TOP w0.114: v1(226.64,14.38) 224.75,16.28 224.75,18.57 v1(224.76,18.58) 224.75,18.59 224.75,36.87 222.37,39.25 CN1.200
  LAY3 w0.127: v1(118.04,45.37) 118.02,45.35 114.67,45.35 113.65,44.33 v1(113.65,44.29)
  LAY4 w0.127: v1(118.04,45.37) 118.31,45.09 118.31,44.9 118.99,44.22 126.15,44.22 126.66,44.73 130.93,44.73 135.02,40.64 135.02,34.15 128.51,27.64 128.51,16.39 129.13,15.76 v1(129.13,15.64)
  BOTTOM w0.102: R784.2 226.66,14.4 v1(226.64,14.38)
  BOTTOM w0.114: R69.2 113.64,44.28 v1(113.65,44.29) 113.9,44.53 U5.7 ; v1(118.04,45.37) 118.48,44.93 R311.2
  BOTTOM w0.127: v1(224.76,18.58) 224.57,18.39 208.5,18.39 206.4,16.29 202.87,16.29 201.83,17.34 201.83,17.34 201.04,18.13 201.04,18.96 195.76,24.24 191.77,24.24 189.74,22.21 189.74,13.34 184.76,8.37 152.17,8.37 149.9,10.64 146.98,10.64 145.04,12.58 131.5,12.58 129.13,14.95 v1(129.13,15.64)
SMBCLK: length 2.7
  BOTTOM w0.114: R310.1 117.69,42.76 117.97,42.48 118.76,42.48 119.13,42.11 U22.14
SMBDATA: length 2.6
  BOTTOM w0.114: U22.15 119.53,42.9 R313.1 118.48,43.16 R311.1
SMC_ONOFF#: length 153.8
  LAY3 w0.102: v1(59.97,75.74) 59.97,74.21 59.11,73.36 59.11,68.82 57.59,67.3 57.59,62.25 58.77,61.06 58.77,57.04 58.04,56.31 v1(58.04,38.66)
  LAY4 w0.102: v1(51.87,76.51) 51.95,76.59 59.61,76.59 59.97,76.23 v1(59.97,75.74) ; v1(112.94,25.47) 112.79,25.62 112.79,26.31 107.08,32.02 107.08,46.57 105.07,48.59 97.18,48.59 87.51,38.92 59.37,38.92 59.11,38.66 v1(58.04,38.66)
  BOTTOM w0.102: D23.P 133.07,18.96 125.96,26.07 114.32,26.07 113.72,25.47 v1(112.94,25.47)
  BOTTOM w0.114: R446.2 v1(59.97,75.74) ; R400.2 51.01,77.36 v1(51.87,76.51)
SMC_SHUTDOWN#: length 139.5
  LAY3 w0.102: v1(42.62,65.24) 41.89,64.51 41.89,41.05 v1(45.06,37.88)
  LAY4 w0.102: v1(113.18,26.05) 113.18,26.56 107.32,32.42 107.32,47.07 105.5,48.89 96.92,48.89 88.06,40.03 47.21,40.03 v1(45.06,37.88)
  BOTTOM w0.102: R395.2 42.72,65.14 v1(42.62,65.24) ; Q46.1 131.14,24.92 R501.2 127.51,24.92 126.03,26.4 113.53,26.4 v1(113.18,26.05)
SOC_COLD_RESET_N: length 194.8
  TOP w0.089: 182.15,49.31 182.15,49.82 181.91,50.05 181.91,50.29 182.01,50.39 182.01,50.66 181.8,50.88 181.51,50.88
  TOP w0.102: U1.Y3 181.51,50.88
  TOP w0.114: 182.15,49.31 182.15,48.69 183.8,47.04 183.8,44.38 v1(184.44,43.73)
  LAY3 w0.102: v1(164.02,50.14) 164.16,50.28 168.34,50.28 169.52,49.1 170.86,49.1 173.4,46.57 173.4,42.38 174.81,40.98 174.81,39.12 176.84,37.09 182.51,37.09 182.73,37.3 183.43,37.3 183.71,37.59 183.71,37.69 184.52,38.5 184.52,43.65 v1(184.44,43.73) ; v1(86.74,60.94) 91.48,60.94 93.47,62.93 114.64,62.93 119,67.29 119,71.2 119.5,71.71 128.76,71.71 128.96,71.91 134.13,71.91 v1(142.79,63.26)
  LAY4 w0.102: v1(86.74,60.94) 86.74,56.4 86.12,55.78 83.88,55.78 82.29,57.37 72.64,57.37 71.7,58.3 68.2,58.3 67.32,57.41 53.52,57.41 52.4,58.54 50.28,58.54 49,59.82 45.54,59.82 v1(43.26,57.54) ; v1(142.79,63.26) 144.37,61.68 148.53,61.68 149.05,61.16 152.26,61.16 153.51,59.92 153.51,54.6 156.25,51.86 156.99,51.86 157.33,51.51 157.33,51.21 158.4,50.14 v1(164.02,50.14)
  BOTTOM w0.102: R454.1 v1(43.26,57.54)
SOC_EXTSMI#: length 148.9
  TOP w0.102: U1.AG53 184.64,76.89 184.33,77.19
  TOP w0.114: 184.33,77.19 184.15,77.38 184.15,81.14 183.79,81.5 R74.1 183.33,82.47 v1(183.33,84.18) 183.33,84.76 R73.1 ; R432.1 78.19,64.07 78.57,64.07 v1(79.14,64.64)
  LAY3 w0.102: v1(183.33,84.18) 177.7,84.18 175.29,86.59 175.29,88.73 167.68,96.34 158.6,96.34 157.96,95.69 119.01,95.69 116.14,92.82 109.21,92.82 108.76,92.37 97.42,92.37 96.66,93.12 v1(88.01,93.12)
  LAY4 w0.102: v1(88.01,93.12) 85.64,90.75 85.64,89.29 80.07,83.73 80.07,65.57 v1(79.14,64.64)
  BOTTOM w0.114: v1(79.14,64.64) 79.14,64.23 78.88,63.96 U32.2
SOC_EXTSMI#_EC: length 15.9
  TOP w0.102: v1(70.14,63.78) 71.21,64.85 72.91,64.85 74.05,63.71 75.59,63.71 v1(76.02,64.14)
  TOP w0.114: v1(76.02,64.14) 76.2,64.32 R432.2
  BOTTOM w0.102: v1(70.14,63.78) 70.14,63.2 D9.P 69.17,63.19 68.59,63.78
  BOTTOM w0.114: 68.59,63.78 68.1,63.78 65.79,66.09 R422.1 ; v1(76.02,64.14) 76.21,63.96 U32.10
SOC_FLASHEN: length 128.7
  TOP w0.102: R43.1 151.8,47.61 151.61,47.8 151.61,48.96 151.29,49.28 149.35,49.28 148.44,48.38 v1(147.28,48.38)
  TOP w0.114: R43.1 152.13,46.94 152.13,46.94 U3.3
  LAY3 w0.102: v1(123.52,45.61) 123.62,45.51 128.61,45.51 129.89,44.22 142.96,44.22 144.57,45.83 144.95,45.83 146.59,47.47 146.59,48.01 146.97,48.38 v1(147.28,48.38)
  LAY4 w0.102: v1(42.72,63.57) 49.37,63.57 51.1,61.84 63.87,61.84 64.81,62.78 72.89,62.78 74.22,61.45 80.98,61.45 81.6,62.06 93.03,62.06 96.46,58.64 96.46,52.04 98.35,50.15 108.78,50.15 113.08,45.85 117.52,45.85 117.78,46.11 120.98,46.11 121.47,45.61 v1(123.52,45.61)
  BOTTOM w0.102: v1(42.72,63.57) R455.1
SOC_RUNTIME_SCI: length 151.3
  TOP w0.089: 184.54,77.43 184.54,78.93
  TOP w0.102: R71.2 184.32,84.37 v1(184.3,84.35) ; U1.AG51 184.83,74.87 184.83,75.16 184.93,75.25 184.93,77.05 184.54,77.43 ; 184.26,81.59 184.54,81.3 184.54,78.93
  TOP w0.114: 184.26,81.59 184.26,84.3 v1(184.3,84.35) ; R417.1 v1(78.98,66.74)
  LAY3 w0.102: v1(184.3,84.35) 183.85,84.79 182.98,84.79 182.69,84.5 178.24,84.5 176.07,86.67 176.07,88.43 167.14,97.36 157.2,97.36 156.55,96.71 150.38,96.71 149.61,95.94 118.92,95.94 116.07,93.09 108.9,93.09 108.51,92.71 98.09,92.71 96.08,94.72 85.76,94.72 v1(85.21,94.17)
  LAY4 w0.102: v1(85.21,94.17) 85.21,89.58 79.61,83.99 79.61,67.37 v1(78.98,66.74)
  BOTTOM w0.114: U30.5 78.89,66.83 v1(78.98,66.74)
SOC_SMB_CLK: length 159.3
  TOP w0.102: v1(186.58,51.88) 186.82,51.88 U1.AM6
  LAY4 w0.127: v1(115.26,47.21) 116.07,48.01 127.07,48.01 128.23,46.86 130.95,46.86 135.89,41.92 135.89,33.41 131.56,29.08 131.56,25.65 130.62,24.71 v1(130.62,16.04)
  BOTTOM w0.114: v1(186.58,51.88) 186.58,51.56 188.61,49.53 188.61,49.21 190.83,47 190.83,40.04 192.2,38.67 ; U5.3 114.25,46.45 R62.1
  BOTTOM w0.127: R62.1 115.01,47.21 v1(115.26,47.21) ; v1(130.62,16.04) 131.18,15.48 137.07,15.48 138.94,13.6 145.76,13.6 147.64,11.72 150.29,11.72 152.62,9.39 184.13,9.39 188.72,13.98 188.72,22.63 193.23,27.14 193.23,37.63 192.2,38.67
SOC_SMB_DATA: length 160.7
  TOP w0.102: U1.AM7 186.74,52.52 v1(186.58,52.52)
  LAY4 w0.127: v1(131.44,16.04) 131,15.6 130.47,15.6 130.08,15.99 130.08,24.91 130.95,25.79 130.95,29.24 135.37,33.66 135.37,41.69 130.71,46.35 128.01,46.35 126.87,47.5 117.42,47.5 116.57,46.65 114.44,46.65 v1(113.92,47.17)
  BOTTOM w0.114: 191,39.13 190.29,39.84 190.29,46.77 188.1,48.96 188.1,49.68 186.13,51.65 186.13,52.07 v1(186.58,52.52)
  BOTTOM w0.127: 191,39.13 192.54,37.59 192.54,27.17 188.21,22.84 188.21,14.32 183.79,9.89 152.84,9.89 150.34,12.39 147.82,12.39 146.01,14.2 139.1,14.2 137.31,15.99 131.49,15.99 v1(131.44,16.04) ; v1(113.92,47.17) 113.52,47.17 R64.1 113.9,46.18 U5.2
SOC_WAKE_SCI: length 116.5
  TOP w0.102: R52.1 v1(180.41,79.95)
  TOP w0.114: R433.1 78.55,63.52 78.69,63.66 79.2,63.66 79.37,63.82 v1(79.41,63.82)
  LAY3 w0.102: v1(84.45,74.59) 84.64,74.4 101.24,74.4 103.06,76.22 108.01,76.22 108.68,76.89 111.53,76.89 112.22,77.58 156.16,77.58 v1(156.68,78.09)
  LAY4 w0.102: v1(84.45,74.59) 84.45,70.11 80.46,66.12 80.46,64.87 v1(79.41,63.82) ; v1(180.41,79.95) 179.77,79.95 177.69,82.03 172.01,82.03 169.25,79.27 157.86,79.27 v1(156.68,78.09)
  BOTTOM w0.114: U32.3 79.11,63.56 79.37,63.82 v1(79.41,63.82)
SODIMM_VREF_CA0: length 1.4
  TOP w0.305: CN1.126 221.19,61.45 v1(221.35,61.28)
SODIMM_VREF_DQ0: length 7.7
  TOP w0.406: 210.42,101.35 CN1.1
  TOP w0.508: R148.1 R152.2 C116.2 C117.2 210.08,101.01 210.42,101.35
SPI_CLK: length 28.7
  TOP w0.114: v1(163.77,42.54) 162.52,42.54 161.29,43.77 161.29,48.59 160.78,49.1 159.49,49.1 159.11,48.72 U2.6 U4.6
  BOTTOM w0.114: R36.1 177.71,46.75 177.42,46.46 177.42,46.01 175.33,43.93 174.46,43.93 172.43,41.89 164.42,41.89 v1(163.77,42.54)
SPI_CS0#: length 29.2
  TOP w0.114: v1(156.57,39.97) U2.1 U4.1 156.57,41.99 156.45,42.11 R568.1
  BOTTOM w0.114: v1(156.57,39.97) 156.57,40.02 156.98,40.42 158.14,40.42 158.43,40.13 158.43,39.9 158.78,39.55 159.43,39.55 161.9,42.02 163.33,42.02 163.96,41.4 172.67,41.4 174.63,43.36 175.47,43.36 R37.1
SPI_SI: length 24.9
  TOP w0.114: v1(162.81,40.99) 162.81,41.36 160.79,43.38 160.79,46.28 160.38,46.69 U4.5 U2.5
  BOTTOM w0.114: R39.1 176.42,42.62 174.99,42.62 172.93,40.57 163.23,40.57 v1(162.81,40.99)
SPI_SO: length 25.1
  TOP w0.114: U4.2 U2.2 v1(157.84,39.95)
  BOTTOM w0.114: v1(157.84,39.95) 158.62,39.18 159.67,39.18 162.11,41.62 163.08,41.62 163.67,41.03 172.84,41.03 174.8,42.99 175.94,42.99 R38.1
SPK_L+: length 258.4
  TOP w0.508: R362.2 v2(242.16,8.74)
  LAY4 w0.508: v1(24.91,39.79) 24.91,40.93 25.97,41.99 27.22,41.99 28.19,42.96 36.51,42.96 46.07,33.4 46.07,14.28 47.76,12.59 57.45,12.59 61.19,8.86 89.62,8.86 92.25,11.5 95.46,11.5 98.1,8.86 112.7,8.86 116.09,12.26 127.8,12.26 131.2,8.86 144.7,8.86 147.31,11.47 150.67,11.47 153.28,8.86 228.92,8.86 232.32,12.26 235.7,12.26 239.1,8.86 239.85,8.86 240.62,9.64 241.42,9.64 242.16,8.89 v2(242.16,8.74)
  BOTTOM w0.178: U25.42 24.63,38.46 24.91,38.75 24.91,38.86
  BOTTOM w0.381: 24.91,38.86 24.91,39.78 v1(24.91,39.79)
SPK_L-: length 255.5
  TOP w0.508: v2(240.94,8.86) R363.2
  LAY4 w0.508: v2(240.94,8.86) 240.31,8.23 238.86,8.23 235.45,11.65 232.57,11.65 229.15,8.23 206.28,8.23 206.28,8.23 152.98,8.23 150.35,10.85 147.65,10.85 145.02,8.23 130.97,8.23 127.55,11.65 116.34,11.65 112.92,8.23 97.81,8.23 95.19,10.85 92.5,10.85 89.88,8.23 60.7,8.23 57.04,11.88 47.58,11.88 45.43,14.03 45.43,33.1 36.21,42.32 28.5,42.32 27.52,41.34 26.33,41.34 25.53,40.55 v1(25.53,39.5)
  BOTTOM w0.178: U25.43 25.03,38.34 25.53,38.85 25.53,38.96
  BOTTOM w0.381: 25.53,38.96 v1(25.53,39.5)
SPK_R+: length 33.9
  TOP w0.508: v1(26.53,39.18) 26.53,39.11 25.16,37.74 22.84,37.74 22.39,37.29 21.12,37.29 20.52,37.88 17.45,37.88 15.8,36.24 15.8,24.38 11.02,19.6 R361.2
  BOTTOM w0.178: U25.45 25.83,38.13 26.53,38.84 v1(26.53,39.18)
SPK_R-: length 37.2
  TOP w0.508: R360.2 10.67,18.35 16.44,24.12 16.44,35.95 17.73,37.24 20.22,37.24 20.83,36.63 22.61,36.63 23.08,37.1 25.46,37.1 27.16,38.8 27.16,39.52 26.86,39.82 v1(26.47,39.82)
  BOTTOM w0.178: v1(26.47,39.82) 26.09,39.44 26.09,38.93 25.43,38.26 U25.44
SPKR: length 190.6
  TOP w0.102: U1.H4 175.02,51.01 v1(174.99,51.01)
  LAY3 w0.102: v1(174.99,51.01) 174.99,48.43 174.47,47.91 174.47,42.75 175.97,41.25 175.97,40.23 176.77,39.43 v1(176.82,39.43)
  LAY4 w0.102: v1(148.23,12.87) 146.06,12.87 143.69,10.51 140.94,10.51 140.53,10.92 130.5,10.92 127.82,13.61 115.89,13.61 112.21,9.93 98.68,9.93 96.04,12.56 91.95,12.56 89.38,9.99 70.64,9.99 67.03,13.6 57.66,13.6 53.08,18.19 50.32,18.19 v1(49.97,18.54) ; v1(173.25,32) 170.56,29.32 169.91,29.32 169.59,29 169.59,27.56 168.84,26.81 167.77,26.81 164.44,23.49 163.09,23.49 162.49,22.89 162.49,18.84 162,18.35 155.04,18.35 154.35,19.05 152.87,19.05 151.86,18.03 151.86,17.34 151.3,16.78 150.69,16.78 v1(150.52,16.95)
  BOTTOM w0.102: v1(150.52,16.95) 150.82,16.65 150.82,14.65 149.05,12.87 v1(148.23,12.87) ; v1(49.97,18.54) 47.25,21.26 41.3,21.26 35.11,27.45 R342.2 ; v1(173.25,32) 172.96,32.29 172.96,36.94 175,38.98 176.33,38.98 176.77,39.43 v1(176.82,39.43)
SSTCMP: length 2.1
  BOTTOM w0.305: U41.15 117.77,87.5 117.63,87.65 R3093.1
STATUS: length 2
  BOTTOM w0.305: R616.1 U41.14
TBCLK: length 2.6
  BOTTOM w0.114: U31.85 45.42,65.86 44.42,66.85 R418.2
TBDATA: length 2.8
  BOTTOM w0.114: U31.86 45.82,66.26 44.34,67.74 R419.2
TP_FUSE_LDO: length 5.9
  TOP w0.102: v1(177.44,59.63) 177.05,59.24 U1.M20
  BOTTOM w0.102: v1(177.44,59.63) 177.03,60.04 172.38,60.04 TP7.1
TP_FUSE_PWR: length 2.3
  TOP w0.102: v1(176.01,59.62) 176.34,59.3 U1.K20
  BOTTOM w0.102: v1(176.01,59.62) 175.08,58.69 TP6.1
TXN0_LVDS: length 2.5
  BOTTOM w0.124: C281.2 157.74,97.81 157.51,97.81 156.95,97.24 156.54,97.24 156.47,97.17 U16.5
TXN1_LVDS: length 2.5
  BOTTOM w0.124: C290.2 157.74,95.28 157.39,95.28 156.62,96.04 156.4,96.04 156.33,95.97 U16.8
TXP0_LVDS: length 2.5
  BOTTOM w0.124: U16.4 156.47,97.57 156.54,97.49 156.84,97.49 157.41,98.06 157.74,98.06 C287.2
TXP1_LVDS: length 2.5
  BOTTOM w0.124: C292.1 157.74,95.53 157.49,95.53 156.72,96.29 156.44,96.29 156.37,96.37 U16.7
USB3_PWRON: length 161
  TOP w0.203: v1(40.1,23.5) R487.2 40.1,21.5 40.29,21.31 U39.4 ; v1(57.44,32.06) 55.89,30.51 55.89,28.76 57.09,27.55 57.09,13.45 58.7,11.85 R492.2 59.28,11.87 U40.4
  LAY3 w0.102: v1(56.63,84.9) 55.76,84.9 55.48,84.62 20.27,84.62 v1(18.33,82.68) ; v1(57.44,32.06) 57.44,56.53 58.16,57.26 v1(58.16,59.75) 58.16,61.17 57.14,62.19 57.14,67.59 58.57,69.02 58.57,74.46 59.48,75.36 59.48,81.99 v1(59.45,82.02)
  BOTTOM w0.102: v1(59.45,82.02) 59.45,82.08 v1(56.63,84.9) 56.63,87.06 53.19,90.51 R482.2 50.21,90.51 U38.4
  BOTTOM w0.114: v1(58.16,59.75) 59.15,59.75 60.64,58.26 U31.31
  BOTTOM w0.203: v1(40.1,23.5) 40.1,25.04 47.12,32.06 v1(57.44,32.06) ; R475.2 U35.4 17.61,83.4 v1(18.33,82.68)
USB3_RX0_N: length 191.2
  TOP w0.101: v1(173.88,63.57) 173.88,63.28 U1.D28
  TOP w0.124: v1(5.48,88.02) 5.74,88.28 5.74,88.66 FIL6.4
  LAY3 w0.112: v1(5.48,88.02) 5.75,88.29 5.75,88.71 6.27,89.23 14.7,89.23 15.08,88.85 27.92,88.85 29.55,87.22 48.54,87.22 50.12,88.8 57.54,88.8 58.05,88.3 66.78,88.3 68.69,86.39 108.32,86.39 108.71,86 114.16,86 114.92,86.76 117.19,86.76 117.43,86.52 123.99,86.52 124.83,85.68 138.79,85.68 138.97,85.86 142.44,85.86 143.76,84.55 147.22,84.55 147.6,84.92 153.81,84.92 160.95,77.79 165.36,77.79 166.21,76.94 167.97,76.94 168.6,76.31 169.61,76.31 171.76,74.16 171.76,72.28 170.92,71.44 170.92,67.08 172.11,65.9 172.11,64.15 173.1,63.16 173.99,63.16 174.08,63.25 174.08,63.37 v1(173.88,63.57)
USB3_RX0_P: length 191.2
  TOP w0.101: U1.F28 174.26,63.31 v1(174.52,63.57)
  TOP w0.124: v1(6.25,88.02) 5.99,88.28 5.99,88.66 FIL6.1
  LAY3 w0.112: v1(174.52,63.57) 174.32,63.37 174.32,63.15 174.09,62.92 173,62.92 171.87,64.05 171.87,65.8 170.68,66.98 170.68,71.54 171.52,72.37 171.52,74.06 169.51,76.07 168.5,76.07 167.87,76.7 166.11,76.7 165.26,77.55 160.85,77.55 153.72,84.68 147.7,84.68 147.32,84.31 143.66,84.31 142.34,85.62 139.07,85.62 138.89,85.44 124.73,85.44 123.89,86.28 117.33,86.28 117.09,86.52 115.02,86.52 114.26,85.76 108.61,85.76 108.22,86.15 68.59,86.15 66.68,88.06 57.95,88.06 57.44,88.56 50.22,88.56 48.64,86.98 29.45,86.98 27.82,88.61 14.98,88.61 14.6,88.99 6.36,88.99 5.99,88.61 5.99,88.29 v1(6.25,88.02)
USB3_RX1_N: length 175.4
  TOP w0.089: U1.D30 173.19,64.39 v1(173.19,64.56)
  TOP w0.124: FIL16.4 32.96,88.18 32.96,87.93 32.84,87.82 30.77,87.82 30.49,88.1 30.49,88.56 30.68,88.75 30.8,88.75 v1(31.01,88.95)
  LAY3 w0.112: v1(173.19,64.56) 173.39,64.56 173.48,64.65 173.48,64.79 173.37,64.9 172.66,64.9 172.41,65.15 172.41,70.37 172.11,70.67 172.11,75.31 168.28,79.14 165.04,79.14 163.77,80.41 163.77,84.61 158.14,90.23 150.55,90.23 148.51,92.27 119.49,92.27 118.13,90.91 114.44,90.91 112.98,89.45 100.91,89.45 100.43,88.96 96.34,88.96 94.22,91.09 85.4,91.09 84.14,92.34 72.98,92.34 71.87,93.45 50.03,93.45 49.42,92.83 44.63,92.83 42.36,90.57 30.99,90.57 30.47,90.06 30.47,89.75 30.6,89.62 31.32,89.62 31.42,89.52 31.42,89.13 31.25,88.95 v1(31.01,88.95)
USB3_RX1_P: length 175.4
  TOP w0.089: U1.F30 173.88,64.38 v1(173.88,64.56)
  TOP w0.124: v1(30.23,88.95) 30.23,88 30.66,87.57 32.95,87.57 33.21,87.83 33.21,88.6 FIL16.1
  LAY3 w0.112: v1(173.88,64.56) 173.79,64.56 173.72,64.64 173.72,64.89 173.47,65.14 172.76,65.14 172.64,65.25 172.64,70.47 172.35,70.77 172.35,75.41 168.38,79.38 165.14,79.38 164.01,80.51 164.01,84.71 158.24,90.47 150.65,90.47 148.61,92.51 119.39,92.51 118.03,91.15 114.34,91.15 112.88,89.69 100.81,89.69 100.33,89.2 96.44,89.2 94.32,91.33 85.5,91.33 84.24,92.58 73.08,92.58 71.97,93.68 49.93,93.68 49.32,93.07 44.53,93.07 42.26,90.81 30.89,90.81 30.23,90.15 v1(30.23,88.95)
USB3_TX0_N: length 176.9
  TOP w0.101: U1.C32 172.66,65.04 172.37,65.33 172.1,65.33 172.01,65.23 171.63,65.23 171.48,65.38 171.48,65.5 170.36,66.62 170.36,67.49 166.72,71.14 166.72,71.15 166.58,71.29 166.5,71.29 166.49,71.31 166.48,71.31
  TOP w0.124: 166.48,71.31 164.62,71.31 163.05,72.88 163.05,73.75 162.18,74.61 162.18,74.82 v1(162.67,75.3) ; C442.2 11.75,86.32 11.75,85.73 v1(11.54,85.52)
  LAY3 w0.112: v1(162.67,75.3) 162.41,75.56 162.41,75.85 162.09,76.17 160.44,76.17 153.73,82.89 148.99,82.89 148.84,82.73 139.83,82.73 139.13,83.43 130.51,83.43 129.87,82.78 124.09,82.78 123.31,83.56 121.49,83.56 120.69,84.36 108.03,84.36 107.56,84.83 67.78,84.83 66.2,86.41 50.44,86.41 49.6,85.57 19.67,85.57 18.31,86.93 11.8,86.93 11.54,86.67 v1(11.54,85.52)
USB3_TX0_P: length 176.9
  TOP w0.101: U1.B32 172.36,65.04 172.44,64.96 172.44,64.82 172.36,64.73 172.13,64.73 171.84,65.02 171.54,65.02 171.25,65.31 171.25,65.41 170.14,66.52 170.14,67.4 166.48,71.05
  TOP w0.124: C443.2 12.01,86.23 12.01,85.82 v1(12.31,85.52) ; 166.48,71.05 164.52,71.05 162.8,72.77 162.8,73.64 161.93,74.51 v1(161.93,75.3)
  LAY3 w0.112: v1(12.31,85.52) 12.52,85.72 12.52,85.86 12.38,86 11.93,86 11.78,86.15 11.78,86.58 11.9,86.69 18.21,86.69 19.57,85.33 49.7,85.33 50.54,86.17 66.1,86.17 67.68,84.59 107.46,84.59 107.93,84.12 120.59,84.12 121.39,83.32 123.21,83.32 123.99,82.55 129.97,82.55 130.61,83.19 139.03,83.19 139.73,82.49 148.94,82.49 149.09,82.65 153.63,82.65 160.34,75.93 161.99,75.93 162.17,75.75 162.17,75.54 v1(161.93,75.3)
USB3_TX1_N: length 153.6
  TOP w0.089: U1.C33 172.32,65.52 171.94,65.91 171.94,65.94 170.8,67.08 170.8,68.02 168.5,70.33 168.5,70.33 168.48,70.35
  TOP w0.101: 167.07,71.76 168.48,70.35
  TOP w0.124: v1(45.06,91.34) 45.06,89.62 44.81,89.37 C2762.2 ; 167.07,71.76 166.76,72.07 164.93,72.07 163.83,73.16 163.83,75.51 162.47,76.88 v1(162.47,79.95)
  LAY3 w0.112: v1(45.06,91.34) 45.06,90.9 45.23,90.74 48.4,90.74 50.16,92.49 63.15,92.49 64.49,91.15 68.25,91.15 71.15,88.26 88.23,88.26 89.81,89.84 94.51,89.84 96.09,88.26 112.91,88.26 114.85,90.2 118.54,90.2 119.49,91.15 145.77,91.15 146.54,90.38 147.21,90.38 150.2,87.39 156.42,87.39 159.18,84.62 162.17,84.62 162.82,83.97 162.82,81.99 162.28,81.45 162.28,80.14 v1(162.47,79.95)
USB3_TX1_P: length 153.8
  TOP w0.089: U1.A33 171.85,65.65 171.73,65.77 171.73,65.84 170.59,66.99 170.59,67.93 169.6,68.92 168.41,70.1
  TOP w0.101: 166.94,71.53 166.98,71.53 168.32,70.19
  TOP w0.102: 168.32,70.19 168.41,70.1 168.41,70.1
  TOP w0.124: v1(161.77,79.95) 162.21,79.51 162.21,76.77 163.58,75.4 163.58,73.06 164.82,71.82 166.66,71.82 166.94,71.53 ; v1(44.29,91.34) 44.81,90.82 44.81,89.73 44.71,89.63 44.36,89.63 C2763.2
  LAY3 w0.112: v1(44.29,91.34) 45.13,90.5 48.5,90.5 50.25,92.26 63.05,92.26 64.4,90.91 68.16,90.91 71.05,88.02 88.33,88.02 89.91,89.6 94.41,89.6 95.99,88.02 113.01,88.02 114.95,89.97 118.64,89.97 119.59,90.92 145.67,90.92 146.44,90.14 147.11,90.14 150.1,87.15 156.32,87.15 159.09,84.38 162.07,84.38 162.58,83.87 162.58,82.09 162.04,81.55 162.04,80.23 v1(161.77,79.95)
